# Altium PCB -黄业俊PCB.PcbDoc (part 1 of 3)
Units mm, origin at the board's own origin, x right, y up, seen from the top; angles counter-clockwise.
Board outline 130 x 100.6 mm, 2 copper layers (Top Layer, Bottom Layer); 47 components, 24 nets, 117 pads, 0 vias.
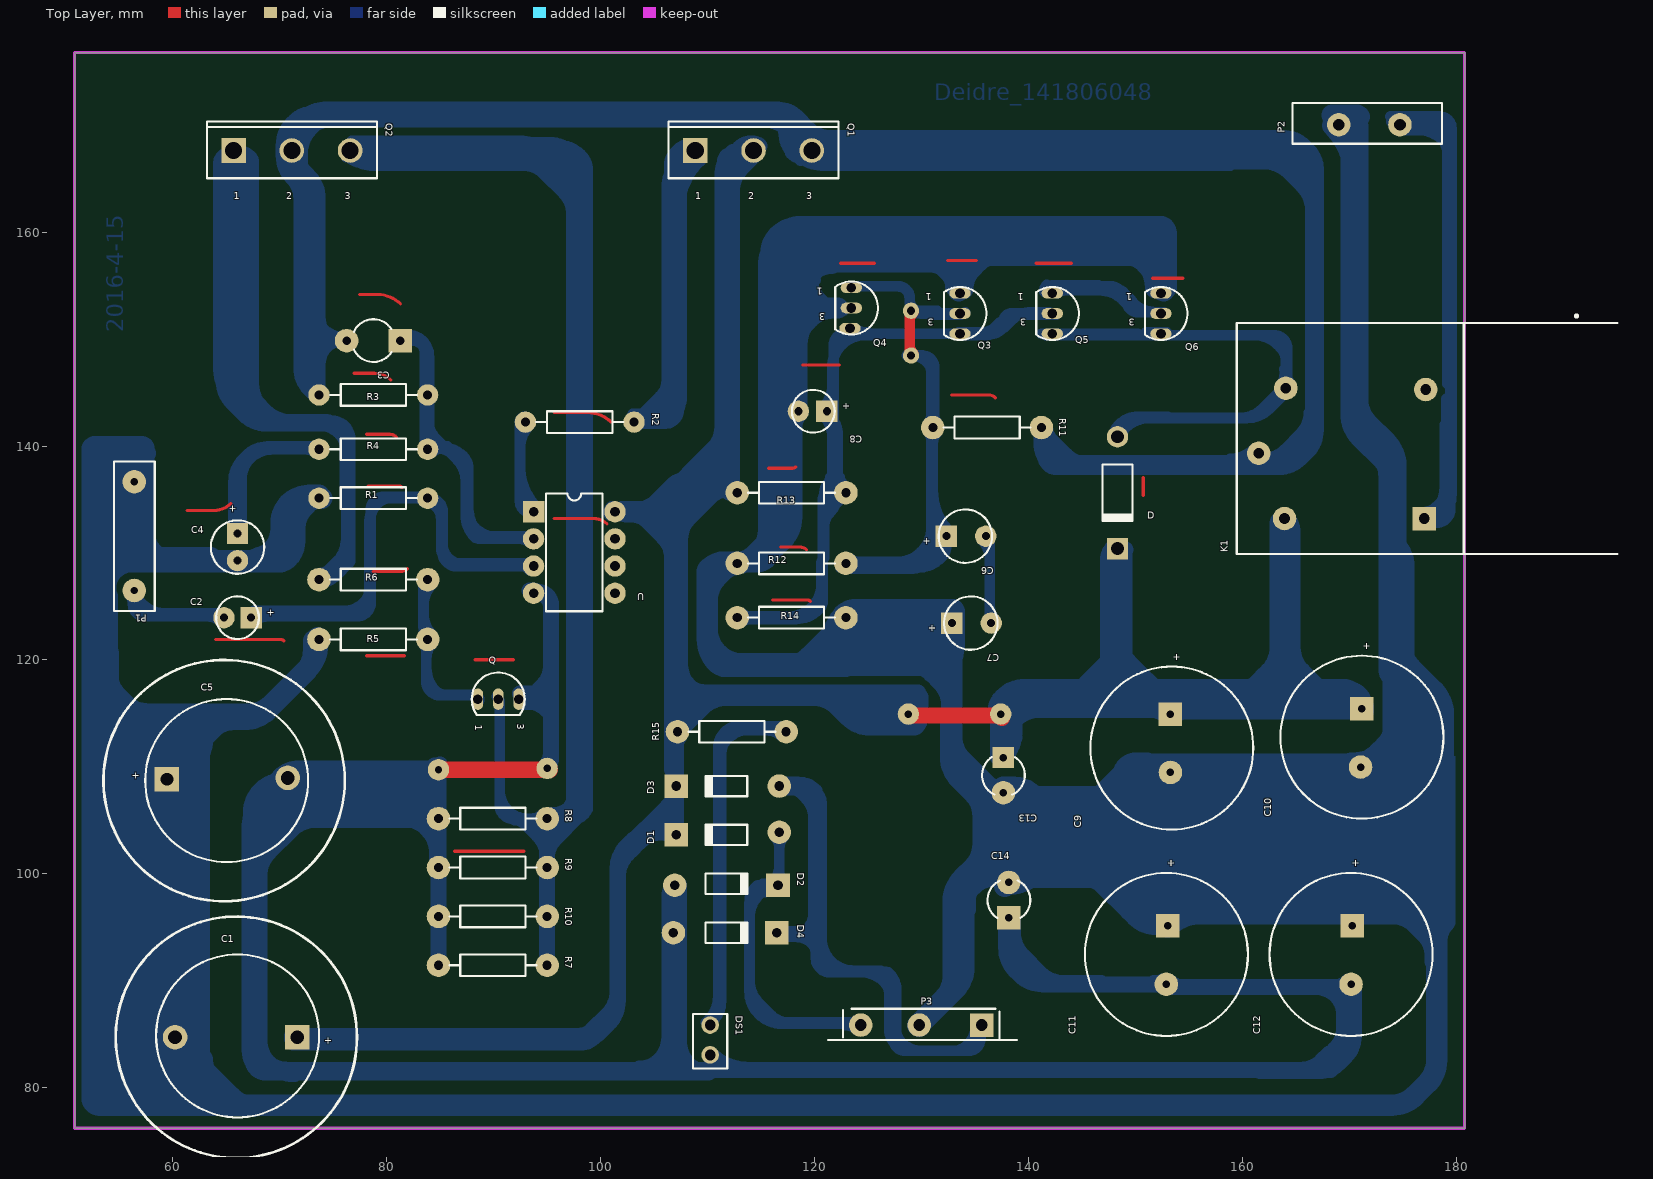
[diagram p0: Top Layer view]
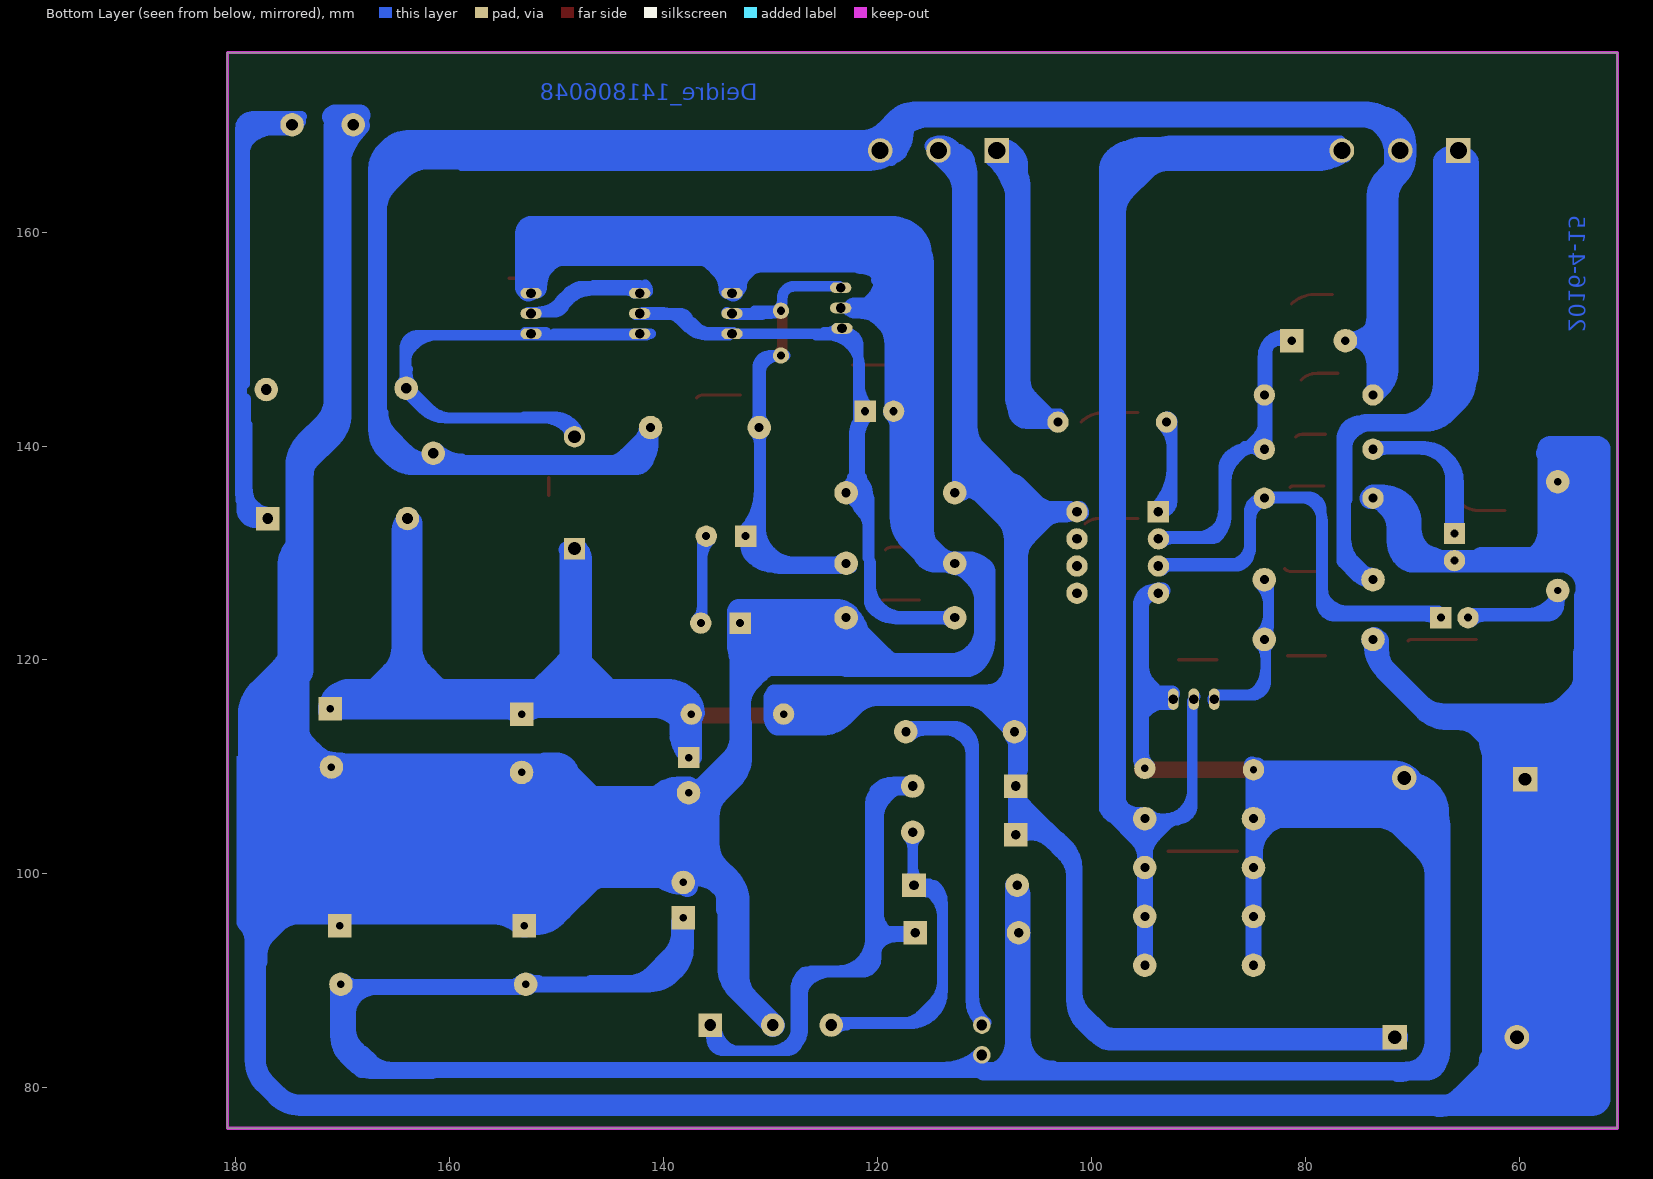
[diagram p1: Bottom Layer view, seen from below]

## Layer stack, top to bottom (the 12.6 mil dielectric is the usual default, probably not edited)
Top Layer: signal copper 0.0356
Dielectric: dielectric 0.32, FR-4, Dk 4.8
Bottom Layer: signal copper 0.0356

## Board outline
50.8,76.2 180.8,76.2 180.8,176.8 50.8,176.8

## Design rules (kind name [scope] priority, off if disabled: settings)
Clearance [All] p1: gap=0.5
ComponentClearance [All] p1: gap=0.254 collisioncheckmode=0
PolygonConnect [All] p1: connectstyle=Relief reliefconductorwidth=0.254 reliefentries=4 polygonreliefangle="90 Angle"
RoutingVias [All] p1: holewidth=0.6 width=1 viastyle="Through Hole" minholewidth=0.711 minwidth=1.27 maxholewidth=0.711 maxwidth=1.27
SolderMaskExpansion [All] p1: expansion=0.102
TestPointUsage [All] p1: valid=0 allowmultiple=FALSE
Testpoint [All] p1: side=15 testpointundercomponent=TRUE minsize=1.016 maxsize=2.54 preferedsize=1.524 minholesize=0 maxholesize=1.016 preferedholesize=0.813 testpointgrid=0.025 style=1023 order=1234567890
Width Width_3 [InNet('GND')] p1: maxlimit=14 minlimit=0.254 preferedwidth=2
Width Width_2 [InNet('+12V')] p2: maxlimit=5 minlimit=0.254 preferedwidth=1.5
Width Width_1 [InNet('-12V')] p3: maxlimit=4 minlimit=0.254 preferedwidth=1.5
Width [All] p4: maxlimit=2 minlimit=0.2 preferedwidth=1
17 further rules are at their usual default settings.

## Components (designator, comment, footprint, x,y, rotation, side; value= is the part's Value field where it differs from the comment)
C1 "Cap Pol1" RB7.6-15#1 66.04,84.836 r0 top
C2 "Cap Pol1" CAPPR1.5-4x5#1 66.04,123.952 r180 top
C3 "Cap" CAPR5-4X5#1 78.74,149.86 r180 top
C4 "Cap Pol1" CAPPR2-5x6.8#1 66.04,130.556 r270 top
C5 "Cap Pol1" RB7.6-15#2 65.024,108.712 r180 top
C6 "Cap Pol1" CAPPR2-5x6.8#2 134.112,131.572 r0 top (schematic designator C7)
C7 "Cap Pol1" CAPPR2-5x6.8#2 134.62,123.444 r0 top
C8 "Cap Pol1" CAPPR1.5-4x5#2 119.888,143.256 r180 top
C9 "Cap Pol1" RB7.6-15#3 153.416,111.76 r90 top
C10 "Cap Pol1" RB7.6-15#4 171.196,112.776 r90 top
C11 "Cap Pol1" RB7.6-15#5 152.908,92.456 r90 top
C12 "Cap Pol1" RB7.6-15#5 170.18,92.456 r90 top
C13 "Cap" CAPR5-4X5#2 137.668,109.22 r270 top
C14 "Cap" CAPR5-4X5#3 138.176,97.536 r90 top
D "1N4001" DIO10.46-5.3x2.8 148.336,135.636 r270 top
D1 "Diode 1N914" DIO7.1-3.9x1.9#1 111.76,103.632 r180 top
D2 "Diode 1N914" DIO7.1-3.9x1.9#2 111.76,99.06 r0 top
D3 "Diode 1N914" DIO7.1-3.9x1.9#3 111.76,108.204 r180 top
D4 "Diode 1N914" DIO7.1-3.9x1.9#3 111.76,94.488 r0 top
DS1 "LED0" CAPR2.54-5.1x3.2 110.236,84.328 r270 top
K1 "Relay-SPDT" DIP-P5/X1.65 177.292,140.716 r180 top
P1 "Header 2" RAD-0.4#1 56.388,131.572 r270 top
P2 "Header 2" RAD-0.4#2 171.704,170.18 r180 top
P3 "Header 3" HDR1X3 132.588,85.852 r180 top
Q "BC547" BCY-W3/E4#1 90.424,116.332 r270 top
Q1 "IRFPC50" TO-247AC 114.3,167.64 r0 top
Q2 "IRFPC50" TO-247AC 71.12,167.64 r0 top
Q3 "9014" BCY-W3/E4#1 133.604,152.4 r180 top
Q4 "9014" BCY-W3/E4#2 123.444,152.908 r180 top
Q5 "8050" BCY-W3/E4#1 142.24,152.4 r180 top
Q6 "8050" BCY-W3/E4#1 152.4,152.4 r180 top
R1 "Res2" AXIAL-0.4#1 78.74,135.128 r180 top
R2 "Res2" AXIAL-0.4#1 98.044,142.24 r0 top
R3 "Res2" AXIAL-0.4#1 78.74,144.78 r180 top
R4 "Res2" AXIAL-0.4#1 78.74,139.7 r0 top
R5 "Res2" AXIAL-0.4#2 78.74,121.92 r0 top
R6 "Res2" AXIAL-0.4#2 78.74,127.508 r180 top
R7 "Res2" AXIAL-0.4#2 89.916,91.44 r0 top
R8 "Res2" AXIAL-0.4#2 89.916,105.156 r0 top
R9 "Res2" AXIAL-0.4#2 89.916,100.584 r0 top
R10 "Res2" AXIAL-0.4#2 89.916,96.012 r0 top
R11 "Res2" AXIAL-0.4#2 136.144,141.732 r0 top
R12 "Res2" AXIAL-0.4#2 117.856,129.032 r180 top
R13 "Res2" AXIAL-0.4#2 117.856,135.636 r0 top
R14 "Res2" AXIAL-0.4#2 117.856,123.952 r0 top
R15 "Res2" AXIAL-0.4#2 112.268,113.284 r180 top
U "NE5532AP" P008 97.536,130.048 r270 top

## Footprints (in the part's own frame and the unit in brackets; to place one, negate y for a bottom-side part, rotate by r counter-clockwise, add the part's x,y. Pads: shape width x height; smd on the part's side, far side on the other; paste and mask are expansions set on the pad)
AXIAL-0.4#1 [mm] "Resistor; 2 Leads"
  round 2 hole 0.85: 1(-5.08,0) 2(5.08,0)
  silkscreen extent -4.06,-1.02 4.06,1.02
AXIAL-0.4#2 [mm] "Resistor; 2 Leads"
  round 2.2 hole 0.85: 1(-5.08,0) 2(5.08,0)
  silkscreen extent -4.06,-1.02 4.06,1.02
BCY-W3/E4#1 [mm] "TO, Flat Index; 3 In-Line, Axial Leads; Body Dia. 4.7mm"
  oval 2x1 hole 0.9: 1(0,-1.905) 2(0,0) 3(0,1.905)
  silkscreen extent -2.48,-2.48 1.5,2.48
BCY-W3/E4#2 [mm] "TO, Flat Index; 3 In-Line, Axial Leads; Body Dia. 4.7mm"
  oval 2x1 hole 0.9: 1(0,-1.905) 2(0,0) 3(0.127,1.905)
  silkscreen extent -2.48,-2.48 1.5,2.48
CAPPR1.5-4x5#1 [mm] "Capacitor, Electrolytic, Radial; Body 4 x 5 mm (Dia.xH typ); Pin Spacing 1.5 mm (typ)"
  rect 2x2 hole 0.75: 1(-1.27,0)
  round 2 hole 0.75: 2(1.27,0)
  silkscreen extent -2,-2 2,2
CAPPR1.5-4x5#2 [mm] "Capacitor, Electrolytic, Radial; Body 4 x 5 mm (Dia.xH typ); Pin Spacing 1.5 mm (typ)"
  rect 2x2 hole 0.75: 1(-1.27,0)
  round 2 hole 0.75: 2(1.397,0)
  silkscreen extent -2,-2 2,2
CAPPR2-5x6.8#1 [mm] "Capacitor, Electrolytic, Radial; Body 5 x 6.8 mm (Dia.xH typ); Pin Spacing 2 mm (typ)"
  rect 2x2 hole 0.75: 1(-1.27,0)
  round 2 hole 0.75: 2(1.27,0)
  silkscreen extent -2.5,-2.5 2.5,2.5
CAPPR2-5x6.8#2 [mm] "Capacitor, Electrolytic, Radial; Body 5 x 6.8 mm (Dia.xH typ); Pin Spacing 2 mm (typ)"
  rect 2x2 hole 0.75: 1(-1.778,0)
  round 2 hole 0.75: 2(1.905,0)
  silkscreen extent -2.5,-2.5 2.5,2.5
CAPR2.54-5.1x3.2 [mm] "Capacitor, Ceramic, Thru-Hole, Dipped Radial; Body 5.1 x 3.2 mm (WxT) Pin Spacing 2.54 mm (typ)"
  round 1.65 hole 1: 1(-1.524,0) 2(1.27,0)
  silkscreen extent -2.55,-1.6 2.55,1.6
CAPR5-4X5#1 [mm] "Capacitor; 2 Leads"
  rect 2.2x2.2 hole 0.8: 1(-2.5,0)
  round 2.2 hole 0.8: 2(2.5,0)
  silkscreen extent -1.69,-2 1.82,2
CAPR5-4X5#2 [mm] "Capacitor; 2 Leads"
  rect 2x2 hole 0.7: 1(-1.651,0)
  round 2.2 hole 0.7: 2(1.651,0)
  silkscreen extent -1.69,-2 1.82,2
CAPR5-4X5#3 [mm] "Capacitor; 2 Leads"
  rect 2.2x2.2 hole 0.7: 1(-1.651,0)
  round 2.2 hole 0.7: 2(1.651,0)
  silkscreen extent -1.69,-2 1.82,2
DIO7.1-3.9x1.9#1 [mm] "Diode, Axial; Body 3.8 x 1.9 mm (LxDia. max), Lead Dia. 0.53 mm (max)"
  round 2.2 hole 0.9: 1(-4.953,-0.254)
  rect 2.2x2.2 hole 0.9: 2(4.699,0)
  silkscreen extent -1.95,-0.95 2.05,0.95
DIO7.1-3.9x1.9#2 [mm] "Diode, Axial; Body 3.8 x 1.9 mm (LxDia. max), Lead Dia. 0.53 mm (max)"
  round 2.2 hole 0.9: 1(-4.826,-0.127)
  rect 2.2x2.2 hole 0.9: 2(4.826,-0.127)
  silkscreen extent -1.95,-0.95 2.05,0.95
DIO7.1-3.9x1.9#3 [mm] "Diode, Axial; Body 3.8 x 1.9 mm (LxDia. max), Lead Dia. 0.53 mm (max)"
  round 2.2 hole 0.9: 1(-4.953,0)
  rect 2.2x2.2 hole 0.9: 2(4.699,0)
  silkscreen extent -1.95,-0.95 2.05,0.95
DIO10.46-5.3x2.8 [mm] "Diode, Axial; Body 5.2 x 2.7 mm (LxDia. max), Lead Dia. 0.86 mm (max)"
  round 2 hole 1.2: 1(-5.23,0)
  rect 2x2 hole 1.2: 2(5.23,0)
  silkscreen extent -2.65,-1.4 2.75,1.4
DIP-P5/X1.65 [mm] "DIP; 5 Round Pins; Row Space 15.24 mm; Pitch 2.54 mm"
  rect 2.2x2.2 hole 1: 1(0.254,7.493)
  round 2.2 hole 1: 2(0.127,-4.572) 3(15.748,1.397) 4(13.335,7.493) 5(13.208,-4.699)
  silkscreen extent -17.8,-11.57 17.8,10.81
HDR1X3 [mm] "Connector; Header; 3 Position"
  rect 2.2x2.2 hole 1.1: 1(-3.048,0)
  round 2.2 hole 1.1: 2(2.794,0) 3(8.255,0)
  silkscreen extent -6.35,-1.52 11.3,1.4
P008 [mm] "DIP; 8 Leads; Row Spacing 7.62 mm; Pitch 2.54 mm"
  rect 2x2 hole 0.9: 1(-3.81,-3.81)
  round 2 hole 0.9: 2(-1.27,-3.81) 3(1.27,-3.81) 4(3.81,-3.81) 5(3.81,3.81) 6(1.27,3.81) 7(-1.27,3.81) 8(-3.81,3.81)
  silkscreen extent -5.5,-2.65 5.5,2.65
RAD-0.4#1 [mm] "Servo Motor; 2 Leads"
  round 2.2 hole 0.7: 1(-5.08,0) 2(5.08,0)
  silkscreen extent -6.98,-1.91 6.98,1.91
RAD-0.4#2 [mm] "Servo Motor; 2 Leads"
  round 2.2 hole 1.1: 1(-3.048,0.127) 2(2.667,0.127)
  silkscreen extent -6.98,-1.91 6.98,1.91
RB7.6-15#1 [mm] "Polarized Capacitor (Radial); 2 Leads"
  rect 2.3x2.3 hole 1.3: 1(5.588,-0.127)
  round 2.3 hole 1.3: 2(-5.842,-0.127)
  silkscreen extent -7.62,-7.62 7.62,7.62
RB7.6-15#2 [mm] "Polarized Capacitor (Radial); 2 Leads"
  rect 2.3x2.3 hole 1.2: 1(5.588,-0.127)
  round 2.3 hole 1.3: 2(-5.715,-0.254)
  silkscreen extent -7.62,-7.62 7.62,7.62
RB7.6-15#3 [mm] "Polarized Capacitor (Radial); 2 Leads"
  rect 2.2x2.2 hole 0.7: 1(3.175,0.127)
  round 2.2 hole 0.7: 2(-2.286,0.127)
  silkscreen extent -7.62,-7.62 7.62,7.62
RB7.6-15#4 [mm] "Polarized Capacitor (Radial); 2 Leads"
  rect 2.2x2.2 hole 0.7: 1(2.667,0)
  round 2.2 hole 0.7: 2(-2.794,0.127)
  silkscreen extent -7.62,-7.62 7.62,7.62
RB7.6-15#5 [mm] "Polarized Capacitor (Radial); 2 Leads"
  rect 2.2x2.2 hole 0.7: 1(2.667,-0.127)
  round 2.2 hole 0.7: 2(-2.794,0)
  silkscreen extent -7.62,-7.62 7.62,7.62
TO-247AC [mm] "SIP with Mounting Hole; 3 Leads; Body 20 x 15.6 x 5 mm (typ); Pitch 5.45 mm"
  rect 2.3x2.3 hole 1.6: 1(-5.45,0)
  round 2.3 hole 1.6: 2(0,0) 3(5.45,0)
  silkscreen extent -7.95,-2.6 7.95,2.7

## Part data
C1 C2 C4 C5 C6 C7 C8 C9 C10 C11 C12: "Polarized Capacitor (Radial)"
C3 C13 C14: "Capacitor"
D: library part "Diode 1N4001", "1 Amp General Purpose Rectifier"
D1 D2 D3 D4: "High Conductance Fast Diode"
DS1: "Typical INFRARED GaAs LED"
K1: "Single-Pole Dual-Throw Relay"
P1 P2: "Header, 2-Pin"
P3: "Header, 3-Pin"
Q Q3 Q4 Q5 Q6: library part 2N3904, "NPN General Purpose Amplifier"
Q1 Q2: "HEXFET Power MOSFET"
R1 R2 R3 R4 R5 R6 R7 R8 R9 R10 R11 R12 R13 R14 R15: "Resistor"
U: "Dual Low-Noise Operational Amplifier"

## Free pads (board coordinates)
  round 2 hole 0.7: 0(94.996,109.855) 1(84.836,109.728) 4(137.414,114.935) 5(128.778,114.935)
  round 1.524 hole 0.762: 0(129.032,152.654) 1(129.032,148.463)

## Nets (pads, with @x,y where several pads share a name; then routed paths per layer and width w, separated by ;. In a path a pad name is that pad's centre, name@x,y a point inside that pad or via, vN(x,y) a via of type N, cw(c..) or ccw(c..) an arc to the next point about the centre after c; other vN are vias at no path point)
+12V: C1.1 C9.1 C10.1 C13.1 D1.2 D3.2 D.2 K1.4 pad.4 pad.5 Q1.2 R13.1 R15.2 U.8 | length 1306.6
  Top Layer w1.5: pad.5@128.778,114.808 136.928,114.808 cw(c136.928,113.941) pad.4@137.541,114.554
  Bottom Layer w1.5: C1.1@71.12,84.582 76.708,84.582 76.835,84.455 ; C1.1@71.12,84.836 97.961,84.836 ccw(c97.961,86.57) 99.187,85.344 100.702,86.859 ccw(c98.534,89.027) 101.6,89.027 101.6,90.678 ; C1.1@71.247,84.201 98.088,84.201 ccw(c98.088,85.935) 99.314,84.709 ; C1.1@71.911,84.426 cw(c72.9,83.437) 72.9,84.836 ; 73.406,84.455 93.98,84.455 ; 73.82,84.201 cw(c73.82,86.901) C1.1@71.911,84.992 ; 92.71,84.582 97.409,84.582 ccw(c97.409,87.648) 99.577,85.48 100.702,86.605 ccw(c98.534,88.773) 101.6,88.773 101.6,90.297 ; 93.98,84.328 97.79,84.328 ccw(c97.79,87.394) 98.663,84.455 ccw(c97.79,87.394) 99.958,85.226 100.702,85.97 ccw(c98.534,88.138) 101.6,88.138 101.6,100.457 cw(c104.666,100.457) 101.727,101.33 cw(c104.666,100.457) 102.498,102.625 102.861,102.988 cw(c105.029,100.82) 103.807,103.632 cw(c105.029,100.82) 105.029,103.886 D1.2@107.315,103.886 ; U.8@101.219,133.985 103.124,133.985 ccw(c103.124,137.051) 105.292,134.883 106.68,136.271 cw(c108.213,134.738) 108.213,136.906 111.633,136.906 111.633,166.624 cw(c112.268,166.624) 112.268,167.259 ; U.8@101.346,133.731 103.899,133.731 cw(c103.899,130.696) 106.045,132.842 ; U.8@101.473,133.858 104.311,133.858 ccw(c104.311,135.592) 105.537,134.366 ccw(c105.537,135.286) 106.187,134.635 106.553,135.001 ; 101.6,97.155 101.6,99.695 cw(c104.666,99.695) 102.498,101.863 104.394,103.759 ccw(c104.394,105.599) 105.695,104.298 106.522,105.125 ccw(c105.221,106.426) 107.061,106.426 ; 101.6,100.584 cw(c104.053,100.584) 102.318,102.318 106.271,106.271 ccw(c104.363,108.179) 107.061,108.179 D3.2@107.061,108.966 ; U.8@101.6,133.858 102.616,133.858 cw(c102.616,130.792) 104.784,132.96 106.29,131.454 cw(c104.122,129.286) 107.188,129.286 107.188,123.698 ; U.8@101.981,133.985 102.26,133.985 cw(c102.26,131.287) 104.168,133.195 105.89,131.473 cw(c103.982,129.565) 106.68,129.565 106.68,109.728 ; U.8@101.981,134.112 103.784,134.112 ccw(c103.784,136.81) 105.692,134.902 110.589,139.799 ccw(c108.681,141.707) 111.379,141.707 111.379,164.998 cw(c114.077,164.998) 112.169,166.906 112.268,167.005 ; 102.108,101.854 ccw(c102.108,102.774) 102.758,102.123 103.623,102.988 cw(c105.791,100.82) 105.791,103.886 ; U.8@102.235,133.858 104.14,133.858 ccw(c104.14,136.924) 106.308,134.756 107.442,135.89 ccw(c107.442,136.503) 107.876,136.07 110.862,139.056 ccw(c108.694,141.224) 111.76,141.224 111.76,144.526 ; 102.616,133.604 102.743,133.604 cw(c102.743,130.538) 104.911,132.706 106.163,131.454 cw(c103.995,129.286) 107.061,129.286 R15.2@107.061,113.411 ; 102.87,102.87 ccw(c102.87,104.403) 103.954,103.319 106.017,105.382 ccw(c104.109,107.29) 106.807,107.29 D3.2@106.807,108.331 ; 105.41,133.223 ccw(c105.41,134.143) 106.06,133.492 ; 106.045,132.768 ccw(c106.479,132.768) 106.172,132.461 ccw(c104.332,134.301) 106.934,134.301 106.934,135.001 ; D1.2@106.68,103.886 105.791,103.886 ; D1.2@106.789,103.411 ccw(c105.791,102.599) 105.791,103.886 ; R15.2@106.807,113.284 106.807,113.538 cw(c109.873,113.538) 107.705,115.706 cw(c108.91,114.501) 108.91,116.205 110.109,116.205 ; R15.2@106.941,113.531 ccw(c105.73,114.742) 107.442,114.742 ; D1.2@107.061,103.632 107.188,103.632 cw(c107.188,103.759) 107.061,103.759 R15.2@107.061,113.284 ; R15.2@107.061,113.665 ccw(c105.221,115.505) 107.823,115.505 108.266,115.505 ccw(c108.266,118.571) 110.434,116.403 cw(c110.57,116.267) 110.57,116.459 ; 107.061,114.436 ccw(c108.34,114.436) R15.2@107.435,113.531 ; R15.2@107.188,113.284 107.188,135.509 cw(c108.458,135.509) 108.458,136.779 111.633,136.779 ; R15.2@107.188,113.411 ccw(c107.188,113.284) R15.2@107.061,113.284 ; 107.188,129.794 107.188,131.699 cw(c110.254,131.699) 108.086,133.867 109.682,135.463 cw(c111.633,133.512) 111.633,136.271 ; 107.188,134.874 cw(c109.947,134.874) 107.996,136.825 110.862,139.691 ccw(c108.694,141.859) 111.76,141.859 111.76,144.018 ; R15.2@107.315,112.776 cw(c108.541,112.776) 107.674,113.643 109.592,115.561 cw(c111.76,113.393) 111.76,116.459 114.554,116.459 128.09,116.459 cw(c128.09,116.025) 128.397,116.332 ; 107.315,117.221 ccw(c107.928,117.834) 107.928,116.967 129.667,116.967 ; 107.315,120.269 107.315,119.761 ccw(c110.381,119.761) 108.213,117.593 108.322,117.484 ccw(c110.49,119.652) 110.49,116.586 ; 107.315,130.937 107.315,132.461 cw(c110.381,132.461) 108.213,134.629 109.211,135.627 cw(c111.379,133.459) 111.379,136.525 R13.1@112.141,136.525 ; 107.315,136.017 cw(c107.315,135.097) 107.965,135.748 108.077,135.636 ; 107.442,121.539 107.442,119.482 ccw(c110.14,119.482) 108.232,117.574 ccw(c109.697,119.039) 109.697,116.967 111.379,116.967 ; 107.442,129.286 107.442,131.343 cw(c110.14,131.343) 108.232,133.251 110.208,135.227 cw(c112.116,133.319) 112.116,136.017 R13.1@112.268,136.017 ; 108.712,135.89 110.735,137.913 ccw(c108.567,140.081) 111.633,140.081 111.633,145.542 ; 109.511,136.689 ccw(c109.294,136.906) 109.601,136.906 ; 109.982,138.303 cw(c110.595,138.303) 110.162,138.737 110.481,139.056 ccw(c108.313,141.224) 111.379,141.224 111.379,143.256 ; 110.481,136.271 ccw(c110.481,138.439) 112.014,136.906 ccw(c111.401,137.519) 112.268,137.519 112.268,163.83 cw(c115.334,163.83) 113.166,165.998 Q1.2@114.554,167.386 ; 110.608,137.024 ccw(c108.44,139.192) 111.506,139.192 111.506,143.637 ; 111.252,116.459 119.888,116.459 cw(c119.888,113.393) 122.056,115.561 123.054,114.563 ccw(c125.222,116.731) 125.222,113.665 ; 111.506,140.843 111.506,165.1 cw(c114.572,165.1) 112.404,167.268 112.649,167.513 ; 111.506,164.338 cw(c111.813,164.645) 111.379,164.645 111.379,165.227 cw(c114.445,165.227) 112.277,167.395 112.395,167.513 Q1.2@114.427,167.513 ; 111.633,136.398 ccw(c111.633,133.639) 109.682,135.59 108.34,134.248 ccw(c110.508,132.08) 107.442,132.08 107.442,114.204 cw(c106.141,114.204) R15.2@107.061,113.284 ; R13.1@112.014,135.636 ccw(c111.401,136.249) 112.268,136.249 112.268,141.986 ; 112.014,136.779 112.014,165.218 cw(c114.182,165.218) 112.649,166.751 ; 112.014,138.11 cw(c110.302,138.11) 111.513,136.899 ccw(c109.689,138.723) 112.268,138.723 ; 112.414,167.513 cw(c112.414,165.246) Q1.2@114.017,166.849 ; 112.936,167.8 cw(c114.087,166.65) Q1.2@114.744,168.138 ; 112.981,167.845 cw(c114.071,166.756) Q1.2@114.873,168.071 ; 123.19,115.57 ccw(c125.03,117.41) 125.03,114.808 127.74,114.808 ccw(c127.74,114.83) 127.756,114.814 ccw(c126.238,113.297) 126.238,115.443 ccw(c126.238,118.509) 128.406,116.341 128.524,116.459 128.524,115.018 cw(c126.79,115.018) 128.016,113.792 cw(c127.709,114.099) 127.709,113.665 125.222,113.665 ; 123.444,115.316 124.736,115.316 ccw(c124.736,116.183) 125.349,115.57 ; 124.495,116.459 cw(c124.495,110.652) pad.5@128.601,114.758 ; 125.095,113.665 129.233,113.665 ccw(c129.233,114.099) 129.54,113.792 ccw(c128.62,114.712) 129.921,114.712 129.921,116.406 ; 125.108,113.665 ccw(c125.108,118.605) pad.5@128.601,115.112 ; 127.381,116.586 129.487,116.586 ccw(c129.487,117.02) 129.794,116.713 cw(c129.487,116.406) 129.921,116.406 ; 128.524,116.152 ccw(c129.995,116.152) pad.5@128.955,115.112 ; pad.5@128.597,115.108 cw(c125.222,118.334) 125.222,113.665 ; pad.5@128.764,115.185 ccw(c128.697,116.406) 129.921,116.406 ; pad.4@136.906,115.053 cw(c139.074,115.053) 137.541,116.586 cw(c139.687,114.44) 139.687,117.475 169.514,117.475 cw(c169.514,116.174) 170.434,117.094 ccw(c170.741,116.787) 170.307,116.787 ; C13.1@137.16,110.871 137.16,113.857 ; 137.16,112.701 ccw(c139.498,112.701) C13.1@137.845,111.048 ; 137.16,113.718 cw(c138.631,113.718) pad.4@137.591,114.758 ; 137.16,113.828 cw(c138.378,113.828) pad.4@137.578,114.746 ; pad.4@137.327,114.701 cw(c136.604,112.75) 138.684,112.75 ; C13.1@137.414,110.744 ccw(c137.414,111.051) 137.631,110.834 137.786,110.989 ccw(c135.618,113.157) 138.684,113.157 138.684,115.062 ; C13.1@137.541,110.744 137.541,113.455 ccw(c135.807,113.455) 137.033,114.681 137.786,115.434 cw(c139.954,113.266) 139.954,116.332 143.637,116.332 ; 137.795,112.395 cw(c140.861,112.395) 138.693,114.563 ; 137.795,112.6 cw(c140.366,112.6) 138.548,114.418 ; 137.795,113.108 cw(c140.366,113.108) 138.548,114.926 cw(c140.716,112.758) 140.716,115.824 145.923,115.824 ; 138.176,112.907 cw(c140.313,112.907) 138.802,114.418 cw(c140.97,112.25) 140.97,115.316 141.224,115.316 ccw(c141.224,118.382) 143.392,116.214 143.501,116.323 cw(c145.669,114.155) 145.669,117.221 170.022,117.221 cw(c170.022,115.92) 170.942,116.84 cw(c169.409,115.307) 171.577,115.307 C10.1@171.577,115.189 ; 139.065,116.078 153.289,116.078 ; 139.245,116.078 167.132,116.078 ccw(c167.132,119.144) 169.3,116.976 ; 140.716,115.316 155.321,115.316 ; 141.732,116.332 168.139,116.332 ; 144.294,116.205 ccw(c144.294,117.072) 144.907,116.459 145.034,116.459 ccw(c145.034,117.072) 145.468,116.639 147.565,118.736 ccw(c145.397,120.904) 148.463,120.904 148.463,122.682 148.463,121.158 ccw(c151.529,121.158) 149.361,118.99 150.994,117.357 ccw(c153.162,119.525) 153.162,116.459 157.353,116.459 ccw(c157.353,111.466) C9.1@153.555,114.708 ; 145.415,117.856 147.438,119.879 ccw(c145.27,122.047) 148.336,122.047 D.2@148.336,130.429 ; 147.447,120.396 147.447,129.33 cw(c149.181,129.33) 147.955,130.556 ccw(c148.262,130.863) 148.262,130.429 148.791,130.429 cw(c148.791,129.995) 149.098,130.302 ccw(c149.405,129.995) 148.971,129.995 148.971,118.723 ccw(c149.838,118.723) 149.225,118.11 ; 147.447,127.656 cw(c151.086,127.656) D.2@148.513,130.229 ; 147.447,129.01 cw(c148.622,129.01) D.2@148.386,130.161 ; D.2@148.159,130.229 cw(c146.199,128.269) 148.971,128.269 ; 149.071,116.332 cw(c149.071,110.717) C9.1@153.042,114.688 ; 149.86,115.57 149.361,116.069 cw(c151.529,118.237) 148.463,118.237 148.463,130.556 148.463,122.047 ccw(c151.529,122.047) 149.361,119.879 152.654,116.586 ; 151.524,115.316 cw(c151.524,113.17) C9.1@153.042,114.688 ; 151.973,117.267 cw(c149.641,114.935) C9.1@152.939,114.935 ; 152.146,117.094 cw(c150.212,115.16) C9.1@152.94,114.961 ; C9.1@152.476,115.748 cw(c152.659,115.565) C9.1@152.659,115.824 ; C9.1@152.908,115.824 167.894,115.824 ; C9.1@153.416,115.189 C10.1@171.069,115.189 ; C9.1@153.536,115.196 cw(c155.054,113.678) 155.054,115.824 ; 155.054,115.316 ccw(c155.054,113.17) C9.1@153.536,114.688 ; 156.28,115.824 ccw(c156.28,111.944) C9.1@153.536,114.688 ; 156.893,116.078 ccw(c156.893,111.331) C9.1@153.536,114.688 ; 157.507,116.332 ccw(c157.507,110.717) C9.1@153.536,114.688 ; 159.512,115.951 cw(c159.819,115.951) 159.602,116.168 162.805,119.371 ccw(c160.637,121.539) 163.703,121.539 K1.4@163.703,133.35 ; 159.512,116.205 ccw(c159.512,119.271) 161.68,117.103 162.932,118.355 ccw(c160.764,120.523) 163.83,120.523 163.83,127.762 ; 161.798,118.364 162.424,118.99 ccw(c160.256,121.158) 163.322,121.158 163.322,132.789 cw(c163.756,132.789) 163.449,133.096 cw(c164.062,132.483) 164.062,133.35 164.196,133.217 cw(c162.932,131.953) 164.719,131.953 164.719,121.158 ccw(c167.785,121.158) 165.617,118.99 166.497,118.11 ; 163.322,130.845 cw(c166.335,130.845) K1.4@164.204,132.976 ; K1.4@163.703,133.477 163.703,116.236 ccw(c165.004,116.236) 164.084,115.316 ; K1.4@163.71,132.976 cw(c161.272,130.538) 164.719,130.538 ; 163.83,122.301 163.83,120.777 ccw(c166.896,120.777) 164.728,118.609 167.386,115.951 ; 163.83,132.071 cw(c165.109,132.071) K1.4@164.204,132.976 ; K1.4@163.83,133.223 163.83,122.047 ccw(c166.896,122.047) 164.728,119.879 ; K1.4@163.859,132.887 cw(c163.527,131.742) 164.719,131.742 ; K1.4@163.957,133.223 163.957,121.92 ccw(c167.023,121.92) 164.855,119.752 169.037,115.57 ; 165.735,116.459 166.624,116.459 ccw(c166.624,119.525) 168.792,117.357 ; 166.059,117.221 cw(c166.059,110.306) C10.1@170.949,115.196 ; 169.545,116.459 ccw(c169.852,116.459) 169.635,116.242 ; 169.738,115.189 ccw(c169.738,116.901) C10.1@170.949,115.69 ; C10.1@170.307,115.57 170.307,116.787 ; C10.1@171.225,115.792 cw(c171.306,116.787) 170.307,116.787 ; C1.1@71.911,84.992 ccw(c73.207,86.288) 73.207,84.455 ; C1.1@71.911,84.992 ccw(c73.207,86.288) 73.207,84.455 ; C1.1@71.911,84.992 ccw(c72.9,85.981) 72.9,84.582 ; C1.1@71.911,84.992 ccw(c72.9,85.981) 72.9,84.582 ; C1.1@71.911,84.992 ccw(c73.207,86.288) 73.207,84.455 ; C1.1@71.911,84.992 ccw(c73.207,86.288) 73.207,84.455 ; C1.1@71.911,84.992 ccw(c73.207,86.288) 73.207,84.455 ; C1.1@71.911,84.992 ccw(c73.207,86.288) 73.207,84.455 ; C1.1@71.911,84.992 ccw(c72.9,85.981) 72.9,84.582 ; C1.1@71.911,84.992 ccw(c73.207,86.288) 73.207,84.455 ; C1.1@71.911,84.992 ccw(c73.207,86.288) 73.207,84.455 ; C1.1@71.911,84.992 ccw(c72.9,85.981) 72.9,84.582 ; C1.1@71.911,84.992 ccw(c73.207,86.288) 73.207,84.455 ; C1.1@71.911,84.992 ccw(c73.207,86.288) 73.207,84.455 ; C1.1@71.911,84.992 ccw(c72.9,85.981) 72.9,84.582 ; U.8@101.523,133.681 cw(c102.563,132.641) 102.563,134.112 ; U.8@101.523,133.681 cw(c102.563,132.641) 102.563,134.112 ; U.8@101.523,133.681 cw(c102.563,132.641) 102.563,134.112 ; 107.061,112.132 cw(c108.34,112.132) R15.2@107.435,113.037 ; 107.061,112.132 cw(c108.34,112.132) R15.2@107.435,113.037 ; 107.061,112.132 cw(c108.34,112.132) R15.2@107.435,113.037 ; 107.061,112.132 cw(c108.34,112.132) R15.2@107.435,113.037 ; 107.061,112.132 cw(c108.34,112.132) R15.2@107.435,113.037 ; 111.513,136.405 ccw(c110.302,135.194) 110.302,136.906 cw(c110.302,135.194) 111.513,136.405 ; 111.513,136.405 ccw(c110.608,135.5) 110.608,136.779 cw(c110.608,135.5) 111.513,136.405 ; 111.633,137.804 ccw(c112.912,137.804) 112.007,136.899 ; 111.633,137.804 ccw(c112.912,137.804) 112.007,136.899 ; 111.633,137.804 ccw(c112.912,137.804) 112.007,136.899 ; 111.633,137.804 ccw(c112.912,137.804) 112.007,136.899 ; 111.633,137.804 ccw(c112.912,137.804) 112.007,136.899 ; 150.911,116.078 cw(c150.911,113.065) C9.1@153.042,115.196 ; 150.911,116.078 cw(c150.911,113.065) C9.1@153.042,115.196 ; 150.911,116.078 cw(c150.911,113.065) C9.1@153.042,115.196 ; 150.911,116.078 cw(c150.911,113.065) C9.1@153.042,115.196 ; 151.831,115.697 cw(c151.831,113.985) C9.1@153.042,115.196 ; 151.831,115.697 cw(c151.831,113.985) C9.1@153.042,115.196 ; 151.831,115.697 cw(c151.831,113.985) C9.1@153.042,115.196 ; C9.1@153.042,114.688 ccw(c149.685,111.331) 149.685,116.078 cw(c149.685,111.331) C9.1@153.042,114.688 ; C9.1@153.536,114.688 cw(c154.747,113.477) 154.747,115.189 ; C9.1@153.536,115.69 ccw(c154.747,116.901) 154.747,115.189 ; C9.1@153.536,115.69 ccw(c154.441,116.595) 154.441,115.316 ; C9.1@153.536,115.69 ccw(c154.441,116.595) 154.441,115.316 ; C9.1@153.536,115.69 ccw(c154.747,116.901) 154.747,115.189 ; C9.1@153.536,115.69 ccw(c154.747,116.901) 154.747,115.189 ; C9.1@153.536,115.69 ccw(c154.441,116.595) 154.441,115.316 ; C9.1@153.536,115.69 ccw(c154.747,116.901) 154.747,115.189 ; K1.4@164.204,132.976 ccw(c165.415,131.765) 163.703,131.765 cw(c165.415,131.765) K1.4@164.204,132.976 ; C10.1@171.069,115.189 ccw(c171.069,115.57) C10.1@171.45,115.57 ; C10.1@171.069,115.189 ccw(c171.069,115.57) C10.1@171.45,115.57 ; C10.1@171.069,115.189 ccw(c171.069,115.57) C10.1@171.45,115.57 ; 171.069,116.595 ccw(c172.348,116.595) C10.1@171.443,115.69 ; 171.069,116.595 ccw(c172.348,116.595) C10.1@171.443,115.69 ; 171.069,116.595 ccw(c172.348,116.595) C10.1@171.443,115.69 ; 171.069,116.595 ccw(c172.348,116.595) C10.1@171.443,115.69 ; U.8@101.523,134.035 ccw(c102.563,135.075) 102.563,133.604 cw(c102.563,135.075) U.8@101.523,134.035 ; 105.603,103.886 cw(c105.603,102.174) 106.814,103.385 ccw(c105.603,102.174) 105.603,103.886 ; 111.633,163.407 cw(c116.501,163.407) 113.059,166.849 ccw(c116.501,163.407) 111.633,163.407
+18V: 
-12V: C5.2 C11.2 C12.2 C14.1 D2.1 D4.1 DS1.2 pad.0@94.996,109.855 pad.1@84.836,109.728 Q.3 R7.1 R8.1 R9.1 R10.1 U.4 | length 714.4
  Top Layer w1.5: pad.1@84.709,109.728 pad.0@95.25,109.728
  Bottom Layer w1.5: 67.183,101.346 67.183,104.546 cw(c69.881,104.546) 67.973,106.454 68.707,107.188 cw(c69.32,106.575) 69.32,107.442 81.051,107.442 ccw(c81.051,110.14) 82.959,108.232 pad.1@84.963,110.236 ; 67.31,102.108 67.31,105.816 cw(c70.008,105.816) 68.1,107.724 68.298,107.922 cw(c70.206,106.014) 70.206,108.712 81.94,108.712 ccw(c81.94,111.41) 83.848,109.502 pad.1@84.455,110.109 ; 67.437,100.584 67.437,104.14 cw(c68.707,104.14) 68.707,105.41 ; 67.437,102.388 cw(c70.441,102.388) 68.317,104.512 cw(c70.485,102.344) 69.612,105.283 71.755,105.283 ; 67.564,85.344 67.564,84.836 ccw(c70.63,84.836) 68.462,82.668 68.825,82.305 ccw(c70.993,84.473) 70.993,81.407 75.692,81.407 ; 67.691,102.87 67.691,103.443 cw(c70.293,103.443) 68.453,105.283 cw(c68.76,104.976) 68.76,105.41 81.915,105.41 ccw(c81.915,108.476) 84.083,106.308 84.328,106.553 ; 67.818,81.915 cw(c69.351,83.448) 67.183,83.448 67.183,104.298 cw(c69.255,104.298) 67.79,105.763 cw(c69.698,103.855) 69.698,106.553 82.274,106.553 ccw(c82.274,109.058) 84.046,107.287 ccw(c82.138,109.195) 84.836,109.195 pad.1@84.836,109.728 ; 68.072,84.201 68.072,83.487 ccw(c70.884,84.709) 68.254,83.133 ccw(c70.884,84.709) 68.716,82.541 68.961,82.296 ; 68.199,102.743 71.374,105.029 ; 68.199,105.664 68.326,105.791 ccw(c68.019,106.098) 68.453,106.098 68.453,108.077 ccw(c68.453,109.303) 69.32,108.436 69.977,109.093 cw(c71.817,107.253) 71.817,109.855 pad.1@84.201,109.855 ; 68.513,82.871 cw(c71.138,84.455) 68.072,84.455 68.072,99.822 cw(c71.138,99.822) 68.97,101.99 71.111,104.131 cw(c73.279,101.963) 73.279,105.029 ; 68.97,82.287 69.079,82.178 ccw(c71.247,84.346) 69.163,82.097 ccw(c71.247,84.346) 71.247,81.28 ; 70.623,103.643 ccw(c68.856,105.41) 71.355,105.41 ; 70.852,104.653 ccw(c70.115,105.677) 71.36,105.474 ; 71.374,81.28 cw(c71.374,84.346) 69.491,81.927 ccw(c70.739,84.727) 70.739,81.661 106.553,81.661 106.553,81.915 ccw(c104.713,83.755) 107.202,82.997 ccw(c104.713,83.755) 107.315,83.755 D2.1@107.315,98.933 ; 72.08,105.644 ccw(c73.279,106.506) 73.279,105.029 ; 72.622,105.41 ccw(c72.929,105.717) 72.929,105.283 ; 73.641,105.029 cw(c73.641,107.296) 72.038,105.693 ; 75.311,105.283 68.707,105.283 ccw(c68.707,104.013) 67.437,104.013 67.437,82.677 ccw(c68.707,82.677) 68.707,81.407 109.982,81.407 ccw(c109.982,81.661) 110.236,81.661 108.917,81.661 cw(c110.031,83.978) 108.213,82.16 cw(c110.381,84.328) 107.415,83.551 cw(c110.381,84.328) 107.315,84.328 ; 79.502,105.156 81.407,105.156 ccw(c81.407,108.222) 83.575,106.054 83.811,106.29 ccw(c81.643,108.458) 84.709,108.458 pad.1@84.709,109.728 ; 79.756,105.156 81.534,105.156 cw(c81.534,102.09) 83.702,104.258 83.811,104.149 cw(c81.643,101.981) 84.709,101.981 R9.1@84.709,100.584 ; 82.804,105.029 73.279,105.029 ; 82.804,105.156 83.566,105.156 cw(c83.566,103.886) 84.836,103.886 R7.1@84.836,91.186 ; 83.312,105.283 72.929,105.283 ; 84.709,101.736 ccw(c85.988,101.736) R9.1@85.083,100.831 ; pad.1@84.709,109.982 84.709,104.521 84.709,109.22 cw(c84.709,109.093) 84.836,109.093 R8.1@84.836,104.902 ; Q.3@92.456,116.84 93.37,116.84 ccw(c93.37,119.538) 95.278,117.63 ccw(c95.04,117.869) 95.377,117.869 95.377,119.38 ; Q.3@92.583,116.078 94.107,116.078 ; Q.3@92.583,116.205 92.837,116.205 cw(c92.837,113.139) 95.005,115.307 ; 92.964,116.332 93.358,116.332 ; U.4@93.345,126.492 93.463,126.492 cw(c93.463,124.324) 94.996,125.857 cw(c94.076,124.937) 95.377,124.937 95.377,110.954 ; 93.726,116.713 94.587,117.574 ccw(c92.679,119.482) 95.377,119.482 95.377,121.539 ; U.4@93.726,126.365 94.107,126.365 cw(c94.107,125.095) 95.377,125.095 95.377,117.348 ; pad.0@94.819,110.032 ccw(c93.473,111.378) 95.377,111.378 ; pad.0@94.869,109.728 ccw(c93.643,110.954) 95.377,110.954 ; pad.0@94.87,110.071 ccw(c94.354,110.954) 95.377,110.954 ; 103.632,81.788 103.71,81.788 ccw(c103.71,84.359) 105.528,82.541 ccw(c103.36,84.709) 106.426,84.709 106.426,97.834 cw(c108.16,97.834) D2.1@106.934,99.06 ; 106.426,92.723 cw(c108.572,92.723) 107.054,94.241 ccw(c108.265,93.03) 106.553,93.03 ; 106.426,96.253 ccw(c108.572,96.253) D4.1@107.054,94.735 ; 106.426,96.862 cw(c109.005,96.862) D2.1@107.181,98.686 ; 106.426,97.722 cw(c107.36,97.722) D2.1@107.05,98.603 ; D4.1@106.553,94.615 cw(c106.68,94.615) 106.68,94.742 D2.1@106.68,98.679 ; D4.1@106.56,94.735 ccw(c104.736,96.559) 107.315,96.559 ; D2.1@106.687,98.686 cw(c105.169,97.168) 107.315,97.168 ; 106.807,90.551 D4.1@106.807,94.234 ; D4.1@106.934,94.488 cw(c106.934,94.234) D4.1@107.188,94.234 ; 107.061,83.365 D4.1@107.061,94.742 ; 107.061,93.03 ccw(c105.349,93.03) 106.56,94.241 cw(c104.736,92.417) 107.315,92.417 ; 110.239,81.661 165.735,81.661 ccw(c165.735,84.727) 167.466,82.196 169.672,84.402 cw(c170.106,84.402) 169.799,84.709 169.799,86.999 ccw(c167.662,86.999) 169.173,88.51 ccw(c167.005,86.342) 167.005,89.408 ; DS1.2@110.289,83.111 ccw(c113.79,86.612) 113.79,81.661 ; DS1.2@110.311,83.058 ccw(c111.718,83.058) 110.723,82.063 ; DS1.2@110.363,82.931 ccw(c111.589,82.931) 110.722,82.064 111.125,81.661 ; 137.922,93.091 ccw(c140.988,93.091) 138.82,90.923 139.183,90.56 ccw(c141.351,92.728) 141.351,89.662 C11.2@153.035,89.662 ; 137.922,94.427 cw(c139.634,94.427) C14.1@138.423,95.638 ; C14.1@137.922,95.885 137.922,93.205 ccw(c140.957,93.205) 138.811,91.059 139.31,90.56 ccw(c141.478,92.728) 141.478,89.662 142.875,89.662 ; C14.1@137.968,95.603 cw(c137.107,94.437) 138.557,94.437 ; C14.1@138.557,95.504 138.557,94.488 ccw(c141.623,94.488) 139.455,92.32 141.088,90.687 ccw(c143.256,92.855) 143.256,89.789 146.812,89.789 ; 161.671,81.534 167.157,81.534 ccw(c167.157,84.232) 169.065,82.324 169.644,82.903 ccw(c167.736,84.811) 170.434,84.811 C12.2@170.434,89.662 ; 163.068,81.661 165.506,81.661 ccw(c165.506,84.359) 167.414,82.451 168.148,83.185 ccw(c168.148,83.492) 168.365,83.275 168.755,83.665 ccw(c166.847,85.573) 169.545,85.573 169.545,86.846 ccw(c167.04,86.846) 168.811,88.618 ccw(c166.903,86.71) 166.903,89.408 164.465,89.408 ; 168.275,81.661 169.043,82.429 ccw(c167.526,83.947) 169.672,83.947 ; C12.2@169.933,89.415 cw(c168.722,88.204) 170.434,88.204 ; C12.2@170.053,89.408 C11.2@153.035,89.408 ; 70.483,105.283 ccw(c70.483,106.682) 71.472,105.693 ; 70.483,105.283 ccw(c70.483,106.682) 71.472,105.693 ; 70.483,105.283 ccw(c70.483,106.682) 71.472,105.693 ; 72.038,105.693 ccw(c73.027,106.682) 73.027,105.283 ; 72.038,105.693 ccw(c73.027,106.682) 73.027,105.283 ; 72.038,105.693 ccw(c73.027,106.682) 73.027,105.283 ; 72.929,105.283 cw(c72.929,106.454) 72.054,105.676 ccw(c72.929,106.454) 72.929,105.283 ; 106.68,95.64 ccw(c107.959,95.64) D4.1@107.054,94.735 ; 106.68,95.64 ccw(c107.959,95.64) D4.1@107.054,94.735 ; 106.68,95.64 ccw(c107.959,95.64) D4.1@107.054,94.735 ; 106.68,95.64 ccw(c107.959,95.64) D4.1@107.054,94.735 ; 106.68,95.64 ccw(c107.959,95.64) D4.1@107.054,94.735 ; 106.68,97.475 cw(c108.392,97.475) D2.1@107.181,98.686 ; 106.68,97.475 cw(c108.392,97.475) D2.1@107.181,98.686 ; 106.68,97.475 cw(c108.392,97.475) D2.1@107.181,98.686 ; 106.68,97.475 cw(c108.392,97.475) D2.1@107.181,98.686 ; 106.68,97.475 cw(c108.392,97.475) D2.1@107.181,98.686 ; D2.1@106.68,98.679 cw(c107.061,98.679) D2.1@107.061,99.06 ; D2.1@106.68,98.679 cw(c107.061,98.679) D2.1@107.061,99.06 ; D2.1@106.68,98.679 cw(c107.061,98.679) D2.1@107.061,99.06 ; 151.756,89.789 cw(c151.756,88.51) C11.2@152.661,89.415 ; 151.756,89.789 cw(c151.756,88.51) C11.2@152.661,89.415 ; 151.756,89.789 cw(c151.756,88.51) C11.2@152.661,89.415 ; C11.2@152.527,89.916 ccw(c153.035,89.916) C11.2@153.035,89.408 ; C11.2@152.527,89.916 ccw(c153.035,89.916) C11.2@152.543,89.789 ; C11.2@152.527,89.916 ccw(c153.035,89.916) C11.2@152.543,89.789 ; C11.2@152.543,89.789 ccw(c153.035,89.916) C11.2@153.035,89.408 ; C11.2@152.543,89.789 ccw(c153.035,89.916) C11.2@153.035,89.408 ; C11.2@153.155,89.909 ccw(c154.366,91.12) 154.366,89.408 ; C11.2@153.155,89.909 ccw(c154.366,91.12) 154.366,89.408 ; C11.2@153.155,89.909 ccw(c154.366,91.12) 154.366,89.408 ; C11.2@153.155,89.909 ccw(c154.366,91.12) 154.366,89.408 ; C11.2@153.155,89.909 ccw(c154.366,91.12) 154.366,89.408 ; 168.722,89.408 ccw(c168.722,91.12) C12.2@169.933,89.909 ; 168.722,89.408 ccw(c168.722,91.12) C12.2@169.933,89.909 ; 168.722,89.408 ccw(c168.722,91.12) C12.2@169.933,89.909 ; 168.722,89.408 ccw(c168.722,91.12) C12.2@169.933,89.909 ; 168.722,89.408 ccw(c168.722,91.12) C12.2@169.933,89.909 ; 83.684,105.283 cw(c83.684,104.004) 84.589,104.909 ccw(c83.684,104.004) 83.684,105.283 ; 84.709,106.308 ccw(c85.988,106.308) 85.083,105.403 cw(c85.988,106.308) 84.709,106.308
-18V: 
